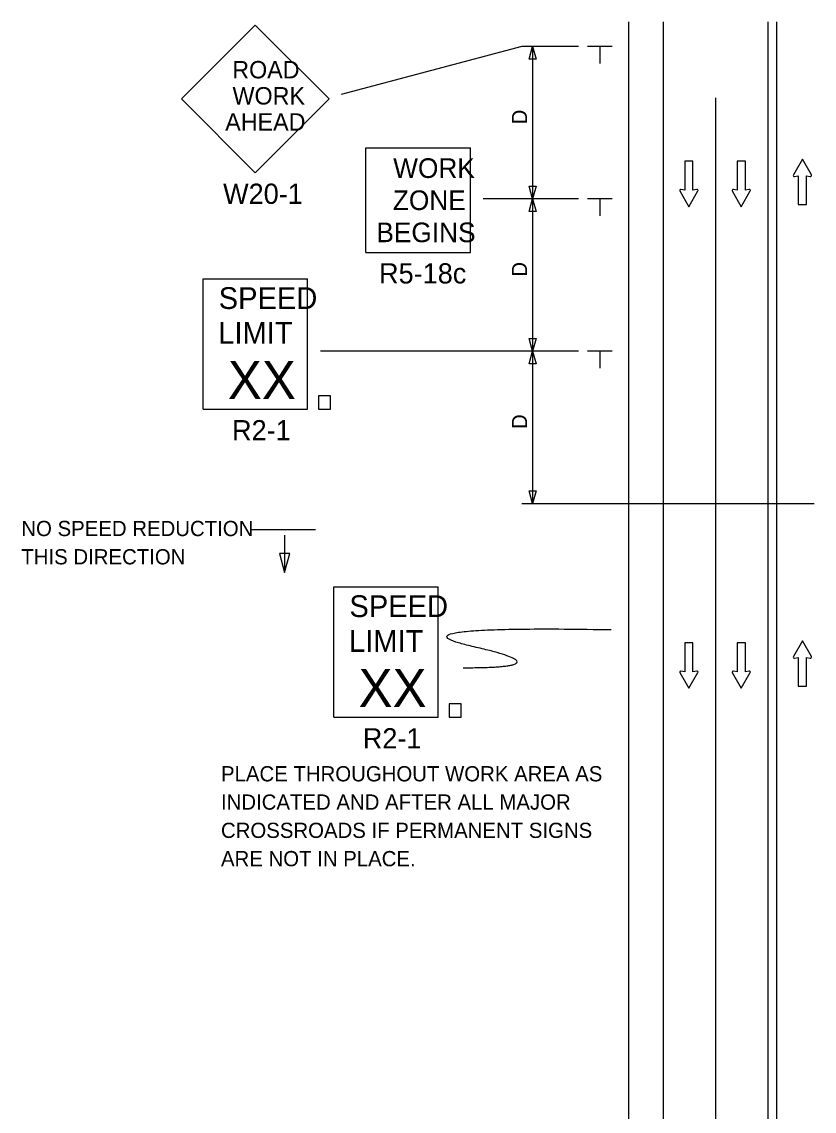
# Model space of a CAD drawing. Extents: x 16747 to 18480, y 5932 to 6927.
# Drawn here: x 16747 to 17111, y 6426 to 6927 of the extents above; entities that cross this region are included whole.
import ezdxf

# ---------------------------------------------------------------- set-up
doc = ezdxf.new("R2010")
doc.units = 0
for name, color, linetype in [('ALI_LEGAL_EX', 7, 'Continuous'), ('MT_SCRATCH_LEVEL_E', 7, 'Continuous'), ('PAVT_EDGE_EX', 7, 'Continuous'), ('TRAFFIC_SIGNS_PR', 7, 'Continuous'), ('TYPICAL_TEXT_DIMEN_PR', 7, 'Continuous')]:
    doc.layers.add(name, color=color, linetype=linetype)

msp = doc.modelspace()

# ---------------------------------------------------------------- linework, layer by layer
at = {"layer": 'ALI_LEGAL_EX'}
msp.add_line((17065.33, 6891.74), (17065.33, 6062.55), dxfattribs=at)
for points in [[(17065.33, 6891.74), (17065.33, 6866.74)], [(17065.33, 6791.74), (17065.33, 6766.74)], [(17065.33, 6691.74), (17065.33, 6666.74)], [(17065.33, 6591.74), (17065.33, 6566.74)], [(17065.33, 6491.74), (17065.33, 6466.74)]]:
    msp.add_lwpolyline(points, dxfattribs=at)
at = {"layer": 'MT_SCRATCH_LEVEL_E'}
for p, q in [((17055, 6862.62), (17051.26, 6862.62)), ((17051.26, 6862.62), (17051.26, 6849.36)), ((17055, 6862.62), (17051.26, 6862.62)), ((17051.26, 6862.62), (17051.26, 6849.36)), ((17055, 6849.36), (17055, 6862.62)), ((17055, 6849.36), (17055, 6862.62)), ((17079.07, 6862.62), (17075.33, 6862.62)), ((17075.33, 6862.62), (17075.33, 6849.36)), ((17079.07, 6862.62), (17075.33, 6862.62)), ((17075.33, 6862.62), (17075.33, 6849.36)), ((17079.07, 6849.36), (17079.07, 6862.62)), ((17079.07, 6849.36), (17079.07, 6862.62)), ((17105.26, 6863.57), (17101.15, 6856.33)), ((17105.26, 6863.57), (17101.15, 6856.33)), ((17109.41, 6856.33), (17105.26, 6863.57)), ((17109.41, 6856.33), (17105.26, 6863.57)), ((17101.63, 6855.64), (17103.41, 6855.96)), ((17101.63, 6855.64), (17103.41, 6855.96)), ((17103.41, 6855.96), (17103.41, 6842.7)), ((17103.41, 6855.96), (17103.41, 6842.7)), ((17107.15, 6842.7), (17107.15, 6855.96)), ((17107.15, 6855.96), (17108.93, 6855.64)), ((17107.15, 6842.7), (17107.15, 6855.96)), ((17107.15, 6855.96), (17108.93, 6855.64)), ((17049, 6848.99), (17053.15, 6841.75)), ((17049, 6848.99), (17053.15, 6841.75)), ((17051.26, 6849.36), (17049.48, 6849.68)), ((17051.26, 6849.36), (17049.48, 6849.68)), ((17053.15, 6841.75), (17057.26, 6848.99)), ((17053.15, 6841.75), (17057.26, 6848.99)), ((17056.78, 6849.68), (17055, 6849.36)), ((17056.78, 6849.68), (17055, 6849.36)), ((17073.07, 6848.99), (17077.22, 6841.75)), ((17073.07, 6848.99), (17077.22, 6841.75)), ((17075.33, 6849.36), (17073.55, 6849.68)), ((17075.33, 6849.36), (17073.55, 6849.68)), ((17077.22, 6841.75), (17081.33, 6848.99)), ((17077.22, 6841.75), (17081.33, 6848.99)), ((17080.85, 6849.68), (17079.07, 6849.36)), ((17080.85, 6849.68), (17079.07, 6849.36)), ((17103.41, 6842.7), (17107.15, 6842.7)), ((17103.41, 6842.7), (17107.15, 6842.7)), ((17055, 6641.3), (17051.26, 6641.3)), ((17051.26, 6641.3), (17051.26, 6628.04)), ((17055, 6641.3), (17051.26, 6641.3)), ((17051.26, 6641.3), (17051.26, 6628.04)), ((17055, 6628.04), (17055, 6641.3)), ((17055, 6628.04), (17055, 6641.3)), ((17079.07, 6641.3), (17075.33, 6641.3)), ((17075.33, 6641.3), (17075.33, 6628.04)), ((17079.07, 6641.3), (17075.33, 6641.3)), ((17075.33, 6641.3), (17075.33, 6628.04)), ((17079.07, 6628.04), (17079.07, 6641.3)), ((17079.07, 6628.04), (17079.07, 6641.3)), ((17105.26, 6642.24), (17101.15, 6635)), ((17105.26, 6642.24), (17101.15, 6635)), ((17109.41, 6635), (17105.26, 6642.24)), ((17109.41, 6635), (17105.26, 6642.24)), ((17101.63, 6634.32), (17103.41, 6634.63)), ((17101.63, 6634.32), (17103.41, 6634.63)), ((17103.41, 6634.63), (17103.41, 6621.38)), ((17103.41, 6634.63), (17103.41, 6621.38)), ((17107.15, 6621.38), (17107.15, 6634.63)), ((17107.15, 6634.63), (17108.93, 6634.32)), ((17107.15, 6621.38), (17107.15, 6634.63)), ((17107.15, 6634.63), (17108.93, 6634.32)), ((17049, 6627.67), (17053.15, 6620.43)), ((17049, 6627.67), (17053.15, 6620.43)), ((17051.26, 6628.04), (17049.48, 6628.35)), ((17051.26, 6628.04), (17049.48, 6628.35)), ((17053.15, 6620.43), (17057.26, 6627.67)), ((17053.15, 6620.43), (17057.26, 6627.67)), ((17056.78, 6628.35), (17055, 6628.04)), ((17056.78, 6628.35), (17055, 6628.04)), ((17073.07, 6627.67), (17077.22, 6620.43)), ((17073.07, 6627.67), (17077.22, 6620.43)), ((17075.33, 6628.04), (17073.55, 6628.35)), ((17075.33, 6628.04), (17073.55, 6628.35)), ((17077.22, 6620.43), (17081.33, 6627.67)), ((17077.22, 6620.43), (17081.33, 6627.67)), ((17080.85, 6628.35), (17079.07, 6628.04)), ((17080.85, 6628.35), (17079.07, 6628.04)), ((17103.41, 6621.38), (17107.15, 6621.38)), ((17103.41, 6621.38), (17107.15, 6621.38))]:
    msp.add_line(p, q, dxfattribs=at)
for centre, start, end in [((17101.56, 6856.1), 150.4248, 279.9638), ((17101.56, 6856.1), 150.4248, 279.9638), ((17109, 6856.1), 260.0362, 29.7731), ((17109, 6856.1), 260.0362, 29.7731), ((17049.41, 6849.22), 80.0362, 209.7731), ((17049.41, 6849.22), 80.0362, 209.7731), ((17056.85, 6849.22), 330.4248, 99.9638), ((17056.85, 6849.22), 330.4248, 99.9638), ((17073.48, 6849.22), 80.0362, 209.7731), ((17073.48, 6849.22), 80.0362, 209.7731), ((17080.92, 6849.22), 330.4248, 99.9638), ((17080.92, 6849.22), 330.4248, 99.9638), ((17101.56, 6634.78), 150.4248, 279.9638), ((17101.56, 6634.78), 150.4248, 279.9638), ((17109, 6634.78), 260.0362, 29.7731), ((17109, 6634.78), 260.0362, 29.7731), ((17049.41, 6627.89), 80.0362, 209.7731), ((17049.41, 6627.89), 80.0362, 209.7731), ((17056.85, 6627.89), 330.4248, 99.9638), ((17056.85, 6627.89), 330.4248, 99.9638), ((17073.48, 6627.89), 80.0362, 209.7731), ((17073.48, 6627.89), 80.0362, 209.7731), ((17080.92, 6627.89), 330.4248, 99.9638), ((17080.92, 6627.89), 330.4248, 99.9638)]:
    msp.add_arc(centre, 0.463, start, end, dxfattribs=at)
at = {"layer": 'PAVT_EDGE_EX'}
for p, q in [((17025.33, 6926.74), (17025.33, 6062.55)), ((17041.33, 6926.74), (17041.33, 6062.55)), ((17089.33, 6926.74), (17089.33, 6062.55)), ((17093.33, 6926.74), (17093.33, 6062.55))]:
    msp.add_line(p, q, dxfattribs=at)
at = {"layer": 'TRAFFIC_SIGNS_PR'}
for p, q in [((16853.86, 6925.24), (16819.92, 6891.3)), ((16887.8, 6891.3), (16853.86, 6925.24)), ((16819.92, 6891.3), (16853.86, 6857.36)), ((16853.86, 6857.36), (16887.8, 6891.3)), ((16904.74, 6820.77), (16904.74, 6868.77)), ((16904.74, 6868.77), (16952.74, 6868.77)), ((16952.74, 6820.77), (16952.74, 6868.77)), ((16904.74, 6820.77), (16952.74, 6820.77)), ((16829.85, 6808.68), (16877.85, 6808.68)), ((16829.85, 6748.68), (16829.85, 6808.68)), ((16877.85, 6748.68), (16877.85, 6808.68)), ((16829.85, 6748.68), (16877.85, 6748.68)), ((16889.91, 6667.1), (16937.91, 6667.1)), ((16889.91, 6607.1), (16889.91, 6667.1)), ((16937.91, 6607.1), (16937.91, 6667.1)), ((16889.91, 6607.1), (16937.91, 6607.1))]:
    msp.add_line(p, q, dxfattribs=at)
for points in [[(16882.86, 6748.68), (16888.46, 6748.68), (16888.46, 6754.85), (16882.86, 6754.85)], [(16942.93, 6607.1), (16948.52, 6607.1), (16948.52, 6613.28), (16942.93, 6613.28)]]:
    msp.add_lwpolyline(points, close=True, dxfattribs=at)
msp.add_open_spline([(16949.36, 6629.89), (16996.59, 6629.89), (16911.57, 6649.24), (17017.37, 6647.41)], degree=2, dxfattribs=at)
at = {"layer": 'TYPICAL_TEXT_DIMEN_PR'}
for p, q in [((16976.33, 6915.37), (16893.26, 6893.28)), ((17002.33, 6915.37), (16976.33, 6915.37)), ((16979.76, 6909.5), (16981.33, 6915.37)), ((16981.33, 6915.37), (16981.33, 6845.37)), ((16981.33, 6915.37), (16982.9, 6909.5)), ((17017.83, 6915.37), (17006.58, 6915.37)), ((17012.2, 6915.37), (17012.2, 6907.58)), ((16981.33, 6909.5), (16979.76, 6909.5)), ((16982.9, 6909.5), (16981.33, 6909.5)), ((16981.33, 6845.37), (16979.76, 6851.23)), ((16979.76, 6851.23), (16981.33, 6851.23)), ((16981.33, 6851.23), (16982.9, 6851.23)), ((16982.9, 6851.23), (16981.33, 6845.37)), ((17002.33, 6845.37), (16958.61, 6845.37)), ((16979.76, 6839.5), (16981.33, 6845.37)), ((16981.33, 6845.37), (16981.33, 6775.37)), ((16981.33, 6845.37), (16982.9, 6839.5)), ((17017.83, 6845.37), (17006.58, 6845.37)), ((17012.2, 6845.37), (17012.2, 6837.58)), ((16981.33, 6839.5), (16979.76, 6839.5)), ((16982.9, 6839.5), (16981.33, 6839.5)), ((16981.33, 6775.37), (16979.76, 6781.23)), ((16979.76, 6781.23), (16981.33, 6781.23)), ((16981.33, 6781.23), (16982.9, 6781.23)), ((16982.9, 6781.23), (16981.33, 6775.37)), ((17002.33, 6775.37), (16883.79, 6775.37)), ((16979.76, 6769.5), (16981.33, 6775.37)), ((16981.33, 6775.37), (16981.33, 6705.37)), ((16981.33, 6775.37), (16982.9, 6769.5)), ((17017.83, 6775.37), (17006.58, 6775.37)), ((17012.2, 6775.37), (17012.2, 6767.58)), ((16981.33, 6769.5), (16979.76, 6769.5)), ((16982.9, 6769.5), (16981.33, 6769.5)), ((16981.33, 6705.37), (16979.76, 6711.23)), ((16979.76, 6711.23), (16981.33, 6711.23)), ((16981.33, 6711.23), (16982.9, 6711.23)), ((16982.9, 6711.23), (16981.33, 6705.37)), ((16976.33, 6705.37), (17110.71, 6705.37)), ((16881.52, 6693.26), (16852.08, 6693.26)), ((16867.34, 6690.76), (16867.34, 6673.63)), ((16867.34, 6682.42), (16864.99, 6682.42)), ((16864.99, 6682.42), (16867.34, 6673.63)), ((16867.34, 6673.63), (16869.7, 6682.42)), ((16869.7, 6682.42), (16867.34, 6682.42))]:
    msp.add_line(p, q, dxfattribs=at)

# ---------------------------------------------------------------- texts
at = {"layer": 'TRAFFIC_SIGNS_PR'}
for s, height, p in [('ROAD', 8, (16843.29, 6900.72)), ('WORK', 8, (16843.42, 6888.72)), ('AHEAD', 8, (16840.06, 6876.72)), ('WORK', 9.021, (16917.24, 6854.98)), ('W20-1', 9.3, (16839.07, 6843.06)), ('ZONE', 9.021, (16917.09, 6840.21)), ('BEGINS', 9.021, (16909.5, 6825.45)), ('R5-18c', 9.3, (16910.75, 6806.47)), ('SPEED', 10, (16837.05, 6794.76)), ('LIMIT', 10, (16836.85, 6778.76)), ('XX', 17.538, (16841.24, 6753.38)), ('R2-1', 9.3, (16843.19, 6734.38)), ('SPEED', 10, (16897.12, 6653.18)), ('LIMIT', 10, (16896.92, 6637.18)), ('XX', 17.538, (16901.31, 6611.8)), ('R2-1', 9.3, (16903.26, 6592.8)), ('PLACE THROUGHOUT WORK AREA AS', 7, (16838.1, 6577.66)), ('INDICATED AND AFTER ALL MAJOR', 7, (16838.1, 6564.66)), ('CROSSROADS IF PERMANENT SIGNS', 7, (16838.1, 6551.66)), ('ARE NOT IN PLACE.', 7, (16838.1, 6538.66))]:
    msp.add_text(s, height=height, dxfattribs=at).set_placement(p)
at = {"layer": 'TYPICAL_TEXT_DIMEN_PR'}
for p in [(16978.77, 6879.58), (16978.77, 6809.58), (16978.77, 6739.58)]:
    msp.add_text('D', height=7, rotation=90, dxfattribs=at).set_placement(p)
for s, p in [('NO SPEED REDUCTION', (16746.36, 6690.38)), ('THIS DIRECTION', (16746.36, 6677.38))]:
    msp.add_text(s, height=7, dxfattribs=at).set_placement(p)

doc.saveas('drawing.dxf')
